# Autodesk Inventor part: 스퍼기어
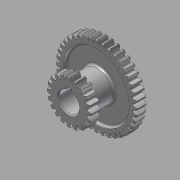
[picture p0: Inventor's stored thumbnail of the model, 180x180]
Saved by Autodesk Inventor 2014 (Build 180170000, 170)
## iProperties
Created: 2015-09
Part Number: 스퍼기어
Material: 강철, 연강
Document SubType Name: Modeling
Designer: mduedu
Density: 7.86 g/cm^3
Mass: 345.726 g
Surface Area: 225.641 cm^2
Volume: 43.9855 cm^3
Appearance: Steel
Author: mduedu
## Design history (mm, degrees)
sketch "스케치1"
  geometry: C1 r 38 at (0, 0); C2 r 40 at (0, 0); C3 r 35.5 at (0, 0); 1 further point
  constraints: 3 centre point, 3 coincident
  dimensions: "d0" = 76 diameter of C1; "d2" = 2 radial gap between concentric circles of C2 C1; "d3" = 71 diameter of C3 (computed from d0)
extrude "돌출1" new body sketch "스케치1" stored distance "d4" = 10; taper "d5" = 0 deg
sketch "스케치2"
  geometry: L1 (0, 35.5)-(0, -35.5); L2 (0, 0)-(40, 0); L3 (0, 0.57)-(39.996, 0.57); L4 (0, 1.57)-(39.969, 1.57); L5 (0, 2.07)-(39.946, 2.07); A1 r 35.5 centre (0, 0) between (0, 35.5) and (0, -35.5) reference; A2 r 40 centre (0, 0) between (40, 0) and (39.946, 2.07) reference; A3 r 9.234 centre (34.93, -7.149) between (39.996, 0.57) and (35.44, 2.07); A4 r 9.234 centre (34.93, 7.149) between (35.44, -2.07) and (39.996, -0.57); A5 r 40 centre (0, 0) between (39.996, -0.57) and (39.996, 0.57); A6 r 35.5 centre (0, 0) between (35.44, -2.07) and (35.44, 2.07); 4 further points
  constraints: 16 point on circle, 10 end point, 6 point on line, 4 centre point, 3 coincident, 3 parallel, 3 symmetric about line, 2 midpoint, 1 perpendicular, 1 vertical, 3 other
  dimensions: "d6" = 0.5 distance between parallel lines of L4 L5; "d8" = 1 distance between parallel lines of L3 L4; "d9" = 1.57 distance between parallel lines of L2 L4
extrude "돌출2" join sketch "스케치2" distance "d10" = 5; taper "d12" = 0 deg; dims "d11" = 5, "d13" = 0
fillet "모깎기1" dims "d17" = 0.5
chamfer "모따기1" distance "d21" = 1; stored, may be unused: second distance "d22" = 2, angle "d23" = 45 deg
sketch "스케치3"
  geometry: C1 r 32.5 at (0, 0); C2 r 15 at (0, 0); 1 further point
  constraints: 2 centre point, 2 coincident
  dimensions: "d27" = 65 diameter of C1; "d28" = 30 diameter of C2
extrude "돌출3" cut sketch "스케치3" distance "d29" = 3; taper "d30" = 0 deg
fillet "모깎기2" dims "d31" = 2
node "작업 평면2"
  node "작업 평면1"
sketch "스케치4"
  geometry: C1 r 15 at (0, 0) reference; 1 further point
extrude "돌출4" join sketch "스케치4" stored distance "d34" = 3; taper "d35" = 0 deg
sketch "스케치5"
  geometry: C1 r 17.5 at (0, 0); C2 r 20 at (0, 0); C3 r 22 at (0, 0); 1 further point
  constraints: 3 centre point, 3 coincident
  dimensions: "d36" = 40 diameter of C2; "d38" = 2 radial gap between concentric circles of C2 C3; "d39" = 35 diameter of C1 (= d36 - 2.5 x d38)
extrude "돌출6" join sketch "스케치5" distance "d46" = 10; taper "d47" = 0 deg
sketch "스케치6"
  geometry: L1 (0, 0)-(0, 22); L2 (-17.5, 0)-(17.5, 0); L3 (-0.57, 0)-(-0.57, 21.993); L4 (-1.57, 0)-(-1.57, 21.944); L5 (-2.07, 0)-(-2.07, 21.902); A1 r 22 centre (0, 0) between (0, 22) and (-0.57, 21.993) reference; A2 r 17.5 centre (0, 0) between (-17.5, 0) and (17.5, 0) reference; A3 r 9.431 centre (7.348, 16.868) between (-0.57, 21.993) and (-2.07, 17.377); A4 r 9.431 centre (-7.348, 16.868) between (2.07, 17.377) and (0.57, 21.993); A5 r 17.5 centre (0, 0) between (2.07, 17.377) and (-2.07, 17.377); A6 r 22 centre (0, 0) between (0.57, 21.993) and (-0.57, 21.993); 4 further points
  constraints: 16 point on circle, 10 end point, 5 point on line, 4 centre point, 3 coincident, 3 symmetric about line, 2 parallel, 2 perpendicular, 1 midpoint, 1 vertical, 3 other
  dimensions: "d40" = 0.5 distance between parallel lines of L4 L5; "d42" = 1 distance between parallel lines of L3 L4; "d43" = 1.57 distance between parallel lines of L1 L4
extrude "돌출5" join sketch "스케치6" distance "d44" = 10; taper "d45" = 0 deg
fillet "모깎기3" dims "d48" = 0.5
chamfer "모따기2" distance "d49" = 1; stored, may be unused: second distance "d50" = 2, angle "d51" = 45 deg
sketch "스케치7"
  geometry: C1 r 10 at (0, 0); 1 further point
  constraints: 1 centre point, 1 coincident
  dimensions: "d55" = 20 diameter of C1
extrude "돌출7" cut sketch "스케치7" stored distance "d56" = 10; taper "d57" = 0 deg
sketch "스케치8"
  geometry: L1 (-9.539, -3)-(-12.8, -3); L2 (-12.8, -3)-(-12.8, 3); L3 (-12.8, 3)-(-9.539, 3); L4 (-9.539, 3)-(-9.539, -3); A1 r 10 centre (0, 0) between (-9.539, -3) and (-9.539, 3) reference; 2 further points
  constraints: 8 end point, 3 point on circle, 2 parallel, 1 horizontal, 1 horizontal alignment, 1 perpendicular
  dimensions: "d58" = 6 distance of L1.end L2.end; "d60" = 22.8 distance from line of point (10, 0) L2
extrude "돌출8" cut sketch "스케치8" stored distance "d61" = 10; taper "d62" = 0 deg
chamfer "모따기3" distance "d63" = 1; stored, may be unused: second distance "d64" = 2, angle "d65" = 45 deg
fillet "모깎기4" dims "d66" = 2
node "솔리드1"
pattern_circular "원형 패턴3" dims "d25" = 360 deg
mirror "대칭1"
pattern_circular "원형 패턴4" dims "d53" = 360 deg
other parameters: "d32" = 5, "d33" = 42
